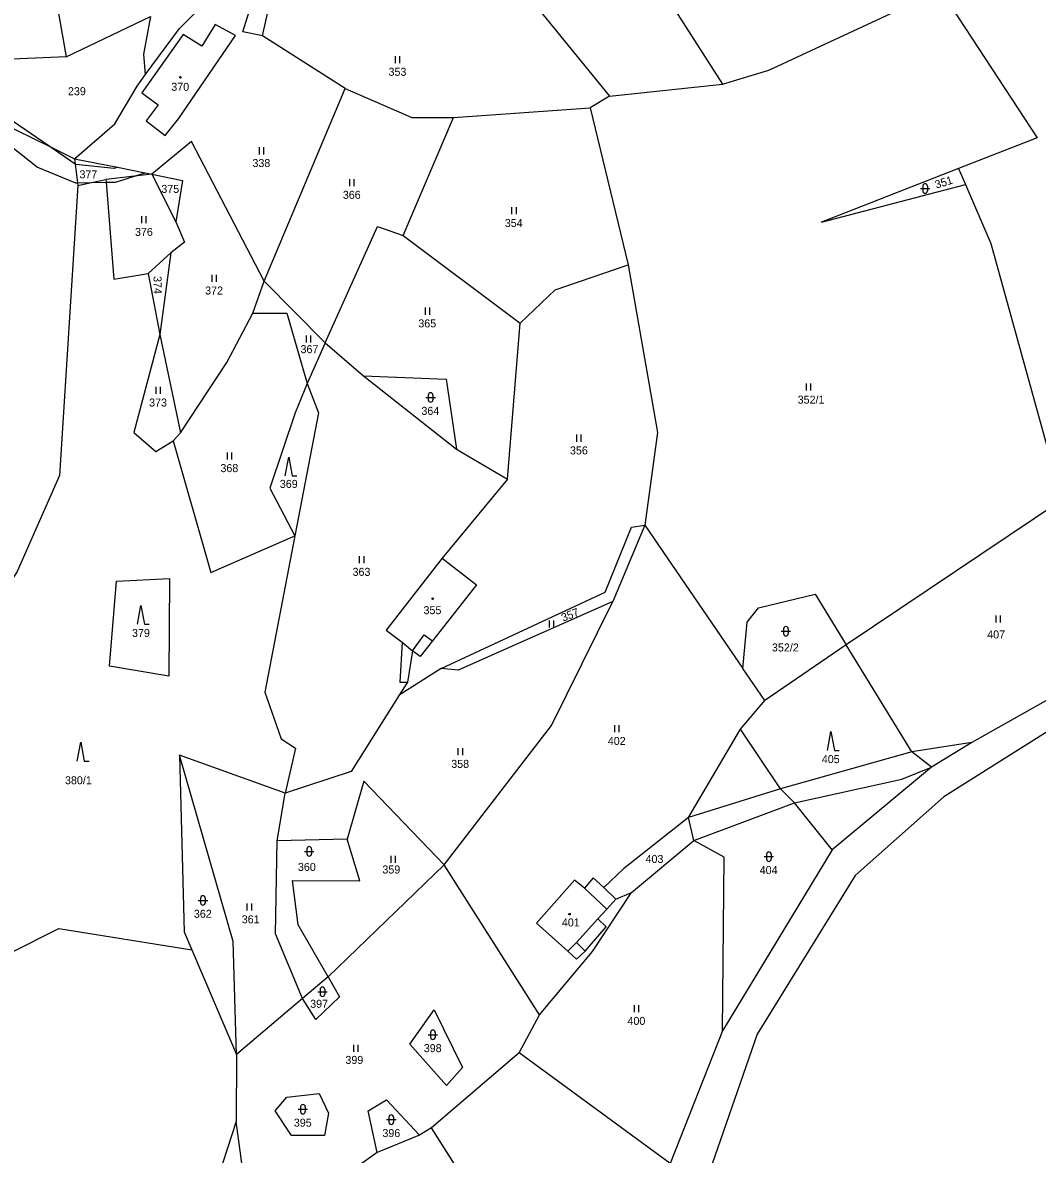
# Model space of a CAD drawing. Extents: x -670359 to -668019, y -978807 to -976674.
# Drawn here: x -669241.5 to -669025.8, y -977399.4 to -977159.1 of the extents above; entities that cross this region are included whole.
import ezdxf

# ---------------------------------------------------------------- set-up
doc = ezdxf.new("R2010")
doc.units = 0
for name, color, linetype in [('Hranice parcel', 7, 'Continuous'), ('Parcelní čísla', 7, 'Continuous'), ('Vnitřní kresba', 7, 'Continuous'), ('Značky budov', 7, 'Continuous'), ('Značky kultur', 7, 'Continuous')]:
    doc.layers.add(name, color=color, linetype=linetype)

msp = doc.modelspace()

# ---------------------------------------------------------------- linework, layer by layer
at = {"layer": 'Hranice parcel'}
for p, q in [((-669200.53, -977159.46), (-669203.37, -977164.12)), ((-669196.2, -977161.83), (-669200.53, -977159.46)), ((-669207.32, -977161.64), (-669216.12, -977173.99)), ((-669208.35, -977179.5), (-669196.2, -977161.83)), ((-669203.37, -977164.12), (-669207.32, -977161.64)), ((-669216.12, -977173.99), (-669212.69, -977176.54)), ((-669212.69, -977176.54), (-669215.22, -977179.95)), ((-669215.22, -977179.95), (-669211.21, -977183.09)), ((-669211.21, -977183.09), (-669208.35, -977179.5))]:
    msp.add_line(p, q, dxfattribs=at)
for points in [[(-669122.64, -977125.54), (-669092.76, -977172.16)], [(-669139.93, -977146.22), (-669116.72, -977174.68)], [(-669208.11, -977160.35), (-669196.78, -977148.94)], [(-669194.66, -977161.03), (-669190.94, -977148.96)], [(-669046.76, -977151.63), (-669025.88, -977183.58)], [(-669082.92, -977169.18), (-669056.93, -977157.17)], [(-669214.32, -977157.79), (-669215.81, -977165.77)], [(-669215.43, -977170.17), (-669208.11, -977160.35)], [(-669190.5, -977161.92), (-669194.66, -977161.03)], [(-669172.92, -977173.09), (-669190.5, -977161.92)], [(-669215.81, -977165.77), (-669215.43, -977170.17)], [(-669092.76, -977172.16), (-669082.92, -977169.18)], [(-669217.12, -977172.57), (-669215.43, -977170.17)], [(-669221.87, -977180.55), (-669217.12, -977172.57)], [(-669190.11, -977214.01), (-669172.92, -977173.09)], [(-669172.92, -977173.09), (-669158.77, -977179.21)], [(-669116.72, -977174.68), (-669092.76, -977172.16)], [(-669116.72, -977174.68), (-669120.89, -977177.15)], [(-669249.76, -977178.51), (-669235.83, -977185.35)], [(-669149.88, -977179.23), (-669120.89, -977177.15)], [(-669120.89, -977177.15), (-669112.76, -977210.54)], [(-669230.44, -977188), (-669221.87, -977180.55)], [(-669160.62, -977204.33), (-669149.88, -977179.23)], [(-669158.77, -977179.21), (-669149.88, -977179.23)], [(-669025.88, -977183.58), (-669042.55, -977190.09)], [(-669235.83, -977185.35), (-669230.44, -977188)], [(-669205.55, -977184.36), (-669213.98, -977191.3)], [(-669190.11, -977214.01), (-669205.55, -977184.36)], [(-669230.44, -977188), (-669221.34, -977189.82)], [(-669230.44, -977188), (-669230.3, -977189.14)], [(-669230.3, -977189.14), (-669229.81, -977193.08)], [(-669221.34, -977189.82), (-669215.43, -977191.01)], [(-669042.55, -977190.09), (-669071.73, -977201.45)], [(-669042.55, -977190.09), (-669041.12, -977193.46)], [(-669229.81, -977193.08), (-669229.74, -977193.65)], [(-669229.74, -977193.65), (-669226.85, -977193.04)], [(-669226.85, -977193.04), (-669223.78, -977192.39)], [(-669217.72, -977191.72), (-669223.78, -977192.39)], [(-669223.78, -977192.39), (-669223.73, -977192.99)], [(-669223.73, -977192.99), (-669222.06, -977213.6)], [(-669213.98, -977191.3), (-669217.72, -977191.72)], [(-669215.43, -977191.01), (-669213.98, -977191.3)], [(-669213.98, -977191.3), (-669208.89, -977201.39)], [(-669213.98, -977191.3), (-669207.5, -977192.59)], [(-669207.5, -977192.59), (-669208.89, -977201.39)], [(-669229.74, -977193.65), (-669233.63, -977255.3), (-669242.61, -977275.64), (-669249.01, -977285.54), (-669255.96, -977296.28), (-669261.61, -977311.07), (-669264.91, -977348.74), (-669264.35, -977366.82), (-669233.76, -977351.5), (-669205.54, -977355.99)], [(-669071.73, -977201.45), (-669041.12, -977193.46)], [(-669041.12, -977193.46), (-669035.72, -977206.03)], [(-669208.89, -977201.39), (-669207.06, -977205.72)], [(-669177.19, -977227.08), (-669166.06, -977202.39)], [(-669166.06, -977202.39), (-669160.62, -977204.33)], [(-669160.62, -977204.33), (-669135.7, -977222.88)], [(-669207.06, -977205.72), (-669209.95, -977207.95)], [(-669035.72, -977206.03), (-669020.61, -977260.48)], [(-669209.95, -977207.95), (-669214.77, -977212.34)], [(-669209.95, -977207.95), (-669212.33, -977225.3)], [(-669222.06, -977213.6), (-669214.77, -977212.34)], [(-669214.77, -977212.34), (-669212.33, -977225.3)], [(-669128.31, -977215.86), (-669112.76, -977210.54)], [(-669112.76, -977210.54), (-669106.55, -977246.16)], [(-669192.54, -977220.8), (-669190.11, -977214.01)], [(-669190.11, -977214.01), (-669177.19, -977227.08)], [(-669135.7, -977222.88), (-669128.31, -977215.86)], [(-669198.1, -977231.26), (-669192.54, -977220.8)], [(-669192.54, -977220.8), (-669185.33, -977220.82)], [(-669185.33, -977220.82), (-669180.98, -977235.71)], [(-669138.45, -977256.07), (-669135.7, -977222.88)], [(-669212.33, -977225.3), (-669217.85, -977246.17)], [(-669212.33, -977225.3), (-669207.92, -977246.2)], [(-669177.19, -977227.08), (-669180.98, -977235.71)], [(-669177.19, -977227.08), (-669169.04, -977234.07)], [(-669207.92, -977246.2), (-669198.1, -977231.26)], [(-669169.04, -977234.07), (-669149.24, -977249.64)], [(-669169.04, -977234.07), (-669151.43, -977234.83)], [(-669180.98, -977235.71), (-669183.56, -977241.95)], [(-669180.98, -977235.71), (-669178.6, -977241.96)], [(-669151.43, -977234.83), (-669149.24, -977249.64)], [(-669183.56, -977241.95), (-669188.9, -977257.93)], [(-669178.6, -977241.96), (-669183.65, -977268.11)], [(-669217.85, -977246.17), (-669213.13, -977250.18)], [(-669207.92, -977246.2), (-669209.44, -977247.87)], [(-669106.55, -977246.16), (-669109.26, -977265.83)], [(-669213.13, -977250.18), (-669209.44, -977247.87)], [(-669209.44, -977247.87), (-669201.45, -977275.9)], [(-669149.24, -977249.64), (-669138.45, -977256.07)], [(-669188.9, -977257.93), (-669183.65, -977268.11)], [(-669138.45, -977256.07), (-669152.28, -977272.84)], [(-669020.61, -977260.48), (-669066.43, -977291.24)], [(-669117.64, -977280.05), (-669112.06, -977266.23)], [(-669109.26, -977265.83), (-669116.04, -977282.06)], [(-669112.06, -977266.23), (-669109.26, -977265.83)], [(-669109.26, -977265.83), (-669088.4, -977296.26)], [(-669201.45, -977275.9), (-669183.65, -977268.11)], [(-669183.65, -977268.11), (-669190.01, -977301.29)], [(-669152.28, -977272.84), (-669164.18, -977288.08)], [(-669152.28, -977272.84), (-669145.01, -977278.46)], [(-669221.55, -977277.68), (-669210.26, -977277.16)], [(-669210.26, -977277.16), (-669210.41, -977297.88)], [(-669222.98, -977295.76), (-669221.55, -977277.68)], [(-669145.01, -977278.46), (-669154.34, -977290.35)], [(-669152.52, -977296.28), (-669117.64, -977280.05)], [(-669116.04, -977282.06), (-669148.92, -977296.61)], [(-669129.1, -977308.34), (-669116.04, -977282.06)], [(-669085.12, -977283.35), (-669073.06, -977280.45)], [(-669073.06, -977280.45), (-669066.43, -977291.24)], [(-669087.5, -977286.44), (-669085.12, -977283.35)], [(-669088.4, -977296.26), (-669087.5, -977286.44)], [(-669164.18, -977288.08), (-669160.83, -977290.65)], [(-669160.83, -977290.65), (-669161.34, -977299.13)], [(-669154.34, -977290.35), (-669156.99, -977293.7)], [(-669066.43, -977291.24), (-669083.76, -977303.03)], [(-669052.5, -977313.92), (-669066.43, -977291.24)], [(-669158.59, -977292.5), (-669159.65, -977299.14)], [(-669156.99, -977293.7), (-669158.59, -977292.5)], [(-669210.41, -977297.88), (-669222.98, -977295.76)], [(-669152.52, -977296.28), (-669161.43, -977301.93)], [(-669148.92, -977296.61), (-669152.52, -977296.28)], [(-669083.76, -977303.03), (-669088.4, -977296.26)], [(-669011.84, -977296.27), (-669039.76, -977311.95)], [(-669159.65, -977299.14), (-669161.43, -977301.93)], [(-669161.34, -977299.13), (-669159.65, -977299.14)], [(-669190.01, -977301.29), (-669186.52, -977311.22)], [(-669161.43, -977301.93), (-669171.65, -977318.15)], [(-669088.91, -977309.17), (-669083.76, -977303.03)], [(-669011.3, -977301.87), (-669045.72, -977323.54)], [(-669151.86, -977337.96), (-669129.1, -977308.34)], [(-669099.94, -977327.87), (-669088.91, -977309.17)], [(-669080.38, -977321.84), (-669088.91, -977309.17)], [(-669186.52, -977311.22), (-669183.48, -977313.15)], [(-669183.48, -977313.15), (-669185.68, -977322.75)], [(-669039.76, -977311.95), (-669048.34, -977317.21)], [(-669196.75, -977354.24), (-669208.15, -977314.68)], [(-669208.15, -977314.68), (-669207.15, -977352.21)], [(-669185.68, -977322.75), (-669208.15, -977314.68)], [(-669048.34, -977317.21), (-669052.5, -977313.92)], [(-669171.65, -977318.15), (-669185.68, -977322.75)], [(-669048.34, -977317.21), (-669069.46, -977334.75)], [(-669168.93, -977320.15), (-669172.5, -977332.47)], [(-669151.86, -977337.96), (-669168.93, -977320.15)], [(-669187.39, -977332.82), (-669185.68, -977322.75)], [(-669077.43, -977324.81), (-669080.38, -977321.84)], [(-669069.46, -977334.75), (-669077.43, -977324.81)], [(-669045.72, -977323.54), (-669064.51, -977340.21)], [(-669099.94, -977327.87), (-669113.75, -977338.79)], [(-669098.84, -977332.75), (-669099.94, -977327.87)], [(-669172.5, -977332.47), (-669187.39, -977332.82)], [(-669169.8, -977341.35), (-669172.5, -977332.47)], [(-669112.08, -977343.83), (-669098.84, -977332.75)], [(-669092.36, -977336.29), (-669098.84, -977332.75)], [(-669187.7, -977352.58), (-669187.39, -977332.82)], [(-669069.46, -977334.75), (-669092.73, -977373.17)], [(-669092.73, -977373.17), (-669092.36, -977336.29)], [(-669151.86, -977337.96), (-669176.52, -977361.74)], [(-669131.63, -977369.78), (-669151.86, -977337.96)], [(-669113.75, -977338.79), (-669117.93, -977342.78)], [(-669182.89, -977350.68), (-669184.14, -977341.31)], [(-669184.14, -977341.31), (-669169.8, -977341.35)], [(-669124.17, -977341.24), (-669132.28, -977350.34)], [(-669122.09, -977342.93), (-669124.17, -977341.24)], [(-669120.24, -977340.69), (-669122.09, -977342.93)], [(-669117.93, -977342.78), (-669120.24, -977340.69)], [(-669064.51, -977340.21), (-669085.36, -977373.91)], [(-669120.37, -977356.37), (-669112.08, -977343.83)], [(-669115.37, -977345.26), (-669117.93, -977342.78)], [(-669115.37, -977345.26), (-669112.08, -977343.83)], [(-669117.35, -977347.4), (-669115.37, -977345.26)], [(-669119.23, -977349.41), (-669117.35, -977347.4)], [(-669117.47, -977351.1), (-669119.23, -977349.41)], [(-669176.52, -977361.74), (-669182.89, -977350.68)], [(-669132.28, -977350.34), (-669125.62, -977356.29)], [(-669121.9, -977356.3), (-669117.47, -977351.1)], [(-669207.15, -977352.21), (-669205.54, -977355.99)], [(-669196.03, -977378.24), (-669196.75, -977354.24)], [(-669181.98, -977366.36), (-669187.7, -977352.58)], [(-669205.54, -977355.99), (-669196.03, -977378.24)], [(-669131.63, -977369.78), (-669120.37, -977356.37)], [(-669125.62, -977356.29), (-669123.74, -977357.96)], [(-669123.74, -977357.96), (-669121.9, -977356.3)], [(-669176.52, -977361.74), (-669181.98, -977366.36)], [(-669176.52, -977361.74), (-669174.13, -977365.98)], [(-669181.98, -977366.36), (-669196.03, -977378.24)], [(-669179.19, -977370.77), (-669181.98, -977366.36)], [(-669174.13, -977365.98), (-669179.19, -977370.77)], [(-669159.19, -977376.03), (-669154.04, -977368.76)], [(-669154.04, -977368.76), (-669148, -977381.02)], [(-669135.98, -977377.85), (-669131.63, -977369.78)], [(-669092.73, -977373.17), (-669103.87, -977401.38)], [(-669151.38, -977384.85), (-669159.19, -977376.03)], [(-669085.36, -977373.91), (-669108.16, -977439.61)], [(-669196.03, -977378.24), (-669196.08, -977392.49)], [(-669135.98, -977377.85), (-669154.61, -977393.8)], [(-669103.87, -977401.38), (-669135.98, -977377.85)], [(-669148, -977381.02), (-669151.38, -977384.85)], [(-669187.82, -977390.19), (-669185.33, -977387.31)], [(-669185.33, -977387.31), (-669178.44, -977386.53)], [(-669178.44, -977386.53), (-669176.46, -977390.7)], [(-669168.05, -977390.16), (-669164.12, -977387.85)], [(-669164.12, -977387.85), (-669157.1, -977395.39)], [(-669184.32, -977395.4), (-669187.82, -977390.19)], [(-669166.15, -977399.05), (-669168.05, -977390.16)], [(-669196.08, -977392.49), (-669200.85, -977407.03)], [(-669194.12, -977407.05), (-669196.08, -977392.49)], [(-669176.46, -977390.7), (-669177.35, -977395.42)], [(-669154.61, -977393.8), (-669157.1, -977395.39)], [(-669144.17, -977410.23), (-669154.61, -977393.8)], [(-669177.35, -977395.42), (-669184.32, -977395.4)], [(-669157.1, -977395.39), (-669166.15, -977399.05)], [(-669166.15, -977399.05), (-669189.99, -977416.1)]]:
    msp.add_lwpolyline(points, dxfattribs=at)
at = {"layer": 'Vnitřní kresba'}
for points in [[(-669190.5, -977161.92), (-669187.9, -977150.17)], [(-669234.31, -977154.34), (-669232.23, -977166.36)], [(-669232.23, -977166.36), (-669214.32, -977157.79)], [(-669232.23, -977166.36), (-669261.75, -977167.6)], [(-669235.83, -977185.35), (-669261.75, -977167.6)], [(-669259.1, -977173.39), (-669238.31, -977189.79)], [(-669230.3, -977189.14), (-669235.83, -977185.35)], [(-669238.31, -977189.79), (-669230.24, -977193.09)], [(-669230.14, -977189.25), (-669230.3, -977189.14)], [(-669221.98, -977190.07), (-669230.14, -977189.25)], [(-669221.34, -977189.82), (-669221.98, -977190.07)], [(-669230.24, -977193.09), (-669229.81, -977193.08)], [(-669229.81, -977193.08), (-669226.85, -977193.04)], [(-669226.85, -977193.04), (-669223.73, -977192.99)], [(-669223.73, -977192.99), (-669221.75, -977192.96)], [(-669221.75, -977192.96), (-669217.72, -977191.72)], [(-669217.72, -977191.72), (-669215.43, -977191.01)], [(-669158.59, -977292.5), (-669156.1, -977289.07)], [(-669156.1, -977289.07), (-669154.34, -977290.35)], [(-669160.83, -977290.65), (-669158.59, -977292.5)], [(-669039.76, -977311.95), (-669052.5, -977313.92)], [(-669052.5, -977313.92), (-669080.38, -977321.84)], [(-669054.6, -977319.75), (-669048.34, -977317.21)], [(-669077.43, -977324.81), (-669054.6, -977319.75)], [(-669080.38, -977321.84), (-669099.94, -977327.87)], [(-669098.84, -977332.75), (-669077.43, -977324.81)], [(-669122.09, -977342.93), (-669117.35, -977347.4)], [(-669123.73, -977354.44), (-669119.23, -977349.41)], [(-669125.62, -977356.29), (-669123.73, -977354.44)], [(-669123.73, -977354.44), (-669121.9, -977356.3)]]:
    msp.add_lwpolyline(points, dxfattribs=at)
at = {"layer": 'Značky budov'}
for centre in [(-669207.94, -977170.72), (-669154.34, -977281.43), (-669125.26, -977348.43)]:
    msp.add_circle(centre, 0.175, dxfattribs=at)
at = {"layer": 'Značky kultur'}
for p, q in [((-669162.28, -977166.18), (-669162.28, -977167.68)), ((-669161.28, -977167.68), (-669161.28, -977166.18)), ((-669191.2, -977185.56), (-669191.2, -977187.06)), ((-669190.2, -977187.06), (-669190.2, -977185.56)), ((-669172.03, -977192.31), (-669172.03, -977193.81)), ((-669171.03, -977193.81), (-669171.03, -977192.31)), ((-669050.68, -977194.32), (-669048.68, -977194.32)), ((-669050.18, -977193.82), (-669050.18, -977194.82)), ((-669049.18, -977193.82), (-669049.18, -977194.82)), ((-669216.2, -977200.19), (-669216.2, -977201.69)), ((-669215.2, -977201.69), (-669215.2, -977200.19)), ((-669137.54, -977198.29), (-669137.54, -977199.79)), ((-669136.54, -977199.79), (-669136.54, -977198.29)), ((-669201.26, -977212.63), (-669201.26, -977214.13)), ((-669200.26, -977214.13), (-669200.26, -977212.63)), ((-669155.95, -977219.61), (-669155.95, -977221.11)), ((-669154.95, -977221.11), (-669154.95, -977219.61)), ((-669181.2, -977225.55), (-669181.2, -977227.05)), ((-669180.2, -977227.05), (-669180.2, -977225.55)), ((-669213.16, -977236.42), (-669213.16, -977237.92)), ((-669212.16, -977237.92), (-669212.16, -977236.42)), ((-669074.95, -977235.74), (-669074.95, -977237.24)), ((-669073.95, -977237.24), (-669073.95, -977235.74)), ((-669155.76, -977238.69), (-669153.76, -977238.69)), ((-669155.26, -977238.19), (-669155.26, -977239.19)), ((-669154.26, -977238.19), (-669154.26, -977239.19)), ((-669123.76, -977246.59), (-669123.76, -977248.09)), ((-669122.76, -977248.09), (-669122.76, -977246.59)), ((-669198, -977250.35), (-669198, -977251.85)), ((-669197, -977251.85), (-669197, -977250.35)), ((-669169.92, -977272.38), (-669169.92, -977273.88)), ((-669168.92, -977273.88), (-669168.92, -977272.38)), ((-669129.59, -977286.07), (-669129.59, -977287.57)), ((-669128.59, -977287.57), (-669128.59, -977286.07)), ((-669034.64, -977284.99), (-669034.64, -977286.49)), ((-669033.64, -977286.49), (-669033.64, -977284.99)), ((-669080.26, -977288.34), (-669078.26, -977288.34)), ((-669079.76, -977287.84), (-669079.76, -977288.84)), ((-669078.76, -977287.84), (-669078.76, -977288.84)), ((-669115.68, -977308.29), (-669115.68, -977309.79)), ((-669114.68, -977309.79), (-669114.68, -977308.29)), ((-669148.95, -977313.16), (-669148.95, -977314.66)), ((-669147.95, -977314.66), (-669147.95, -977313.16)), ((-669181.56, -977335.09), (-669179.56, -977335.09)), ((-669181.06, -977334.59), (-669181.06, -977335.59)), ((-669180.06, -977334.59), (-669180.06, -977335.59)), ((-669163.24, -977336.04), (-669163.24, -977337.54)), ((-669162.24, -977337.54), (-669162.24, -977336.04)), ((-669083.87, -977336.21), (-669081.87, -977336.21)), ((-669083.37, -977335.71), (-669083.37, -977336.71)), ((-669082.37, -977335.71), (-669082.37, -977336.71)), ((-669204.14, -977345.5), (-669202.14, -977345.5)), ((-669203.64, -977345), (-669203.64, -977346)), ((-669202.64, -977345), (-669202.64, -977346)), ((-669193.79, -977346.17), (-669193.79, -977347.67)), ((-669192.79, -977347.67), (-669192.79, -977346.17)), ((-669178.75, -977364.91), (-669176.75, -977364.91)), ((-669178.25, -977364.41), (-669178.25, -977365.41)), ((-669177.25, -977364.41), (-669177.25, -977365.41)), ((-669111.5, -977367.74), (-669111.5, -977369.24)), ((-669110.5, -977369.24), (-669110.5, -977367.74)), ((-669154.79, -977373.53), (-669154.79, -977374.53)), ((-669153.79, -977373.53), (-669153.79, -977374.53)), ((-669155.29, -977374.03), (-669153.29, -977374.03)), ((-669171.14, -977376.15), (-669171.14, -977377.65)), ((-669170.14, -977377.65), (-669170.14, -977376.15)), ((-669182.9, -977389.86), (-669180.9, -977389.86)), ((-669182.4, -977389.36), (-669182.4, -977390.36)), ((-669181.4, -977389.36), (-669181.4, -977390.36)), ((-669164.12, -977392.07), (-669162.12, -977392.07)), ((-669163.62, -977391.57), (-669163.62, -977392.57)), ((-669162.62, -977391.57), (-669162.62, -977392.57))]:
    msp.add_line(p, q, dxfattribs=at)
for points in [[(-669185.67, -977255.34), (-669184.92, -977251.34), (-669184.17, -977255.34), (-669183.17, -977255.34)], [(-669217.08, -977286.86), (-669216.33, -977282.86), (-669215.58, -977286.86), (-669214.58, -977286.86)], [(-669070.45, -977313.65), (-669069.7, -977309.65), (-669068.95, -977313.65), (-669067.95, -977313.65)], [(-669229.86, -977315.91), (-669229.11, -977311.91), (-669228.36, -977315.91), (-669227.36, -977315.91)]]:
    msp.add_lwpolyline(points, dxfattribs=at)
for centre in [(-669207.94, -977170.72), (-669154.34, -977281.43), (-669125.26, -977348.43)]:
    msp.add_circle(centre, 0.175, dxfattribs=at)
for centre, start, end in [((-669049.68, -977193.82), 0, 180), ((-669049.68, -977194.82), 180, 0), ((-669154.76, -977238.19), 0, 180), ((-669154.76, -977239.19), 180, 0), ((-669079.26, -977287.84), 0, 180), ((-669079.26, -977288.84), 180, 0), ((-669180.56, -977334.59), 0, 180), ((-669180.56, -977335.59), 180, 0), ((-669082.87, -977335.71), 0, 180), ((-669082.87, -977336.71), 180, 0), ((-669203.14, -977345), 0, 180), ((-669203.14, -977346), 180, 0), ((-669177.75, -977364.41), 0, 180), ((-669177.75, -977365.41), 180, 0), ((-669154.29, -977373.53), 0, 180), ((-669154.29, -977374.53), 180, 0), ((-669181.9, -977389.36), 0, 180), ((-669181.9, -977390.36), 180, 0), ((-669163.12, -977391.57), 0, 180), ((-669163.12, -977392.57), 180, 0)]:
    msp.add_arc(centre, 0.5, start, end, dxfattribs=at)

# ---------------------------------------------------------------- texts
at = {"layer": 'Parcelní čísla'}
for s, p in [('353', (-669163.71, -977170.38)), ('239', (-669231.83, -977174.5)), ('370', (-669209.87, -977173.57)), ('338', (-669192.63, -977189.76)), ('377', (-669229.39, -977192.15)), ('375', (-669211.99, -977195.25)), ('366', (-669173.42, -977196.51)), ('376', (-669217.59, -977204.39)), ('354', (-669139, -977202.49)), ('372', (-669202.69, -977216.83)), ('365', (-669157.38, -977223.81)), ('367', (-669182.41, -977229.29)), ('373', (-669214.59, -977240.62)), ('352/1', (-669076.76, -977240.01)), ('364', (-669156.72, -977242.39)), ('356', (-669125.15, -977250.79)), ('368', (-669199.43, -977254.55)), ('369', (-669186.81, -977257.9)), ('363', (-669171.35, -977276.58)), ('355', (-669156.27, -977284.72)), ('379', (-669218.22, -977289.56)), ('407', (-669036.48, -977289.87)), ('352/2', (-669082.22, -977292.64)), ('402', (-669117.11, -977312.49)), ('358', (-669150.38, -977317.36)), ('405', (-669071.63, -977316.35)), ('380/1', (-669232.46, -977320.84)), ('360', (-669182.96, -977339.24)), ('403', (-669109.09, -977337.55)), ('359', (-669165.01, -977339.79)), ('404', (-669084.83, -977339.91)), ('362', (-669205.07, -977349.2)), ('361', (-669194.9, -977350.37)), ('401', (-669126.87, -977351.03)), ('397', (-669180.36, -977368.31)), ('400', (-669112.93, -977371.94)), ('398', (-669156.22, -977377.73)), ('399', (-669172.87, -977380.23)), ('395', (-669183.83, -977393.56)), ('396', (-669165.01, -977395.77))]:
    msp.add_text(s, height=1.7, dxfattribs=at).set_placement(p)
for s, rotation, p in [('351', 17.0257, (-669047.29, -977194.35)), ('374', 271.1019, (-669213.65, -977212.93)), ('357', 21.5014, (-669126.59, -977286.33))]:
    msp.add_text(s, height=1.7, rotation=rotation, dxfattribs=at).set_placement(p)

doc.saveas('drawing.dxf')
